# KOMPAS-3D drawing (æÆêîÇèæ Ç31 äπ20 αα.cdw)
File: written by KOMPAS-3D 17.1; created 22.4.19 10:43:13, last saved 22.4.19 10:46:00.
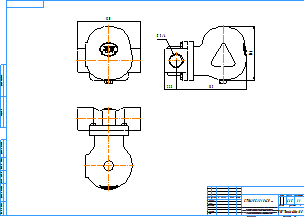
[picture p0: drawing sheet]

Sheet 1: A2, landscape

Title block, sheet 1: name: СТИМАКС А31 Ду20 рр; material: Внимание! Данный продукт является объектом авторского права ООО «Торговый Дом АДЛ». / Запрещается изменение, копирование, распространение / (в том числе путем копирования на другие сайты и ресурсы в Интернете) / или любое иное использование информации и объектов без предварительного / согласия правообладателя (ООО «Торговый Дом АДЛ»).; mass: 6,15; sheets: 1; organisation: ООО "Торговый дом АДЛ"; sheet format: A2; stored path: \\adlc.lan\data\АДЛ_ПКД\3D-модели\ADL production\Конденсатоотводчики СТИМАКС\Поплавковые\Серия А31\KOMPAS 2D\СТИМАКС А31 Ду20 рр.cdw

Views: Вид 1, Проекционный вид 2, Проекционный вид 3
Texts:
  user
Dimensions and other numbers on the sheet: 120; 22,5; 135; 104; 1:1; 1; 6,15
